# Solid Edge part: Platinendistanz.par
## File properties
Author: heha
Template: Normal.par
Last saved by: heha
Revision: 5
Application: Solid Edge
Genauigkeit: 0,990
Teilflächenrmatvorlage: Model Default
Coef. of Thermal Exp: 0.0
Thermal Conductivity: 0.0
Specific Heat: 0.0
Modulus of Elasticity: 0.0
Poission's Ratio: 0.0
Yield Stress: 0.0
Ultimate Stress: 0.0
Elongation: 0.0
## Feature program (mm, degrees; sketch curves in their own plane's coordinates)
sketch for "unnamed Protrusion 1" plane through (0, 0, 0) normal (0, 0, 1) x-axis (1, 0, 0)
  circle centre (0, 0) radius 25.5
extrude "unnamed Protrusion 1" add finite 16.8 along +normal
sketch for "unnamed Cutout 1" #1 plane through (0, 0, 0) normal (0, 0, 1) x-axis (1, 0, 0)
  circle centre (24.1278, -4.2544) radius 4
sketch for "unnamed Cutout 1" #2 plane through (0, 0, 0) normal (0, 0, 1) x-axis (1, 0, 0)
  circle centre (-20.0692, -14.0526) radius 4
sketch for "unnamed Cutout 1" #3 plane through (0, 0, 0) normal (0, 0, 1) x-axis (1, 0, 0)
  circle centre (2.1353, 24.4068) radius 4
extrude "unnamed Cutout 1" cut through along +normal
fillet "Rund_1" radius 1
thinwall "Dünnwand1"  Thickness = 1.4 mm
sketch for "unnamed Cutout 2" plane through (0, 0, 0) normal (0, -1, 0) x-axis (1, 0, 0)
  line (-6.1, 0) -> (-6.1, 11)
  line (-6.1, 11) -> (6.1, 11)
  line (6.1, 11) -> (6.1, 0)
  line (6.1, 0) -> (-6.1, 0)
  dimension (linear) = 6.1
  dimension (linear) = 6.1
extrude "unnamed Cutout 2" cut through along +normal
sketch for "unnamed Cutout 3" plane through (0, -0.0293, 16.8) normal (0, 0, 1) x-axis (1, 0, 0)
  line (0, 0.0293) -> (-24.6425, -6.5279)
  arc centre (0, 0.0293) radius 25.5 from (-24.6425, -6.5279) to (-6.6425, 24.649) cw
  line (0, 0.0293) -> (-6.6425, 24.649)
extrude "unnamed Cutout 3" cut through along -normal
sketch for "Mikrocontroller" plane through (0, 0, 0) normal (0, 0, 1) x-axis (1, 0, 0)
  line (0, 0) -> (0, 0)
  line (0, 0) -> (0, 0)
  line (9.74, 14.06) -> (20.74, 14.06)
  line (20.74, 14.06) -> (20.74, -6.44)
  line (20.74, -6.44) -> (9.74, -6.44)
  line (9.74, -6.44) -> (9.74, 14.06)
  dimension (linear) = 20.74
  dimension (linear) = 20.74
extrude "Mikrocontroller" cut finite 8.2 along +normal
sketch for "Potis" #1 plane through (0, 0, 0) normal (0, 0, 1) x-axis (1, 0, 0)
  line (-5.89, -11.51) -> (-11.89, -11.51)
  line (-11.89, -11.51) -> (-11.89, -21.51)
  line (-11.89, -21.51) -> (-5.89, -21.51)
  line (-5.89, -21.51) -> (-5.89, -11.51)
sketch for "Potis" #2 plane through (0, 0, 0) normal (0, 0, 1) x-axis (1, 0, 0)
  line (5.89, -11.51) -> (5.89, -21.51)
  line (5.89, -21.51) -> (11.89, -21.51)
  line (11.89, -21.51) -> (11.89, -11.51)
  line (11.89, -11.51) -> (5.89, -11.51)
sketch for "Potis" #3 plane through (0, 0, 0) normal (0, 0, 1) x-axis (1, 0, 0)
  line (3.35, 18.97) -> (3.35, 8.97)
  line (3.35, 8.97) -> (9.35, 8.97)
  line (9.35, 8.97) -> (9.35, 18.97)
  line (9.35, 18.97) -> (3.35, 18.97)
  dimension (linear) = 9.35
  dimension (linear) = 3.35
extrude "Potis" cut finite 10 along +normal
chamfer "Fase_1" setback 1
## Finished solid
Body 1: solid body, 43 faces, 123 edges, 82 vertices.
  Faces by surface: plane 22, cylinder 20, cone 1
  Edges by curve: line 66, circle 55, intersection 2
Bounding box of the edges (mm): 50.132 x 50.832 x 16.800, from (-24.6425, -25.5, 0) to (25.489, 25.332, 16.8).
Cylindrical faces by radius (mm): R1 x6, R4 x3, R5.4 x3, R24.1 x4, R25.5 x4
Conical faces (half-angle, radius in mm at the cone's reference point): 45 deg R25.1 x1
Planar faces by outward normal: +x 2, +y 3, +z 1, -x 5, -y 1, -z 8, oblique 2
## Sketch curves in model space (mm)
circle centre (0, 0, 0) radius 24.5
line (0, 0, 0) -> (-20.0692, -14.0526, 0)
line (0, 0, 0) -> (24.1278, -4.2544, 0)
line (0, 0, 0) -> (2.1353, 24.4068, 0)
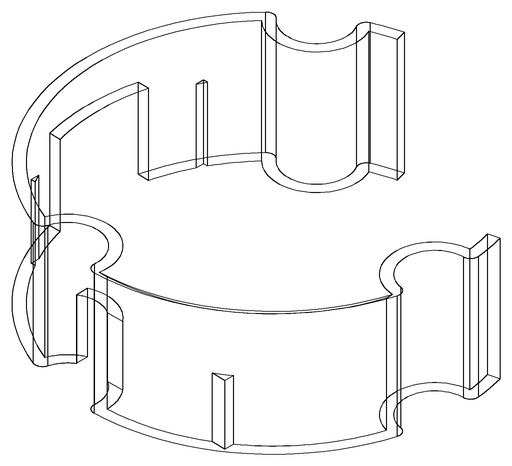
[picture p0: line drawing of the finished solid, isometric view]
